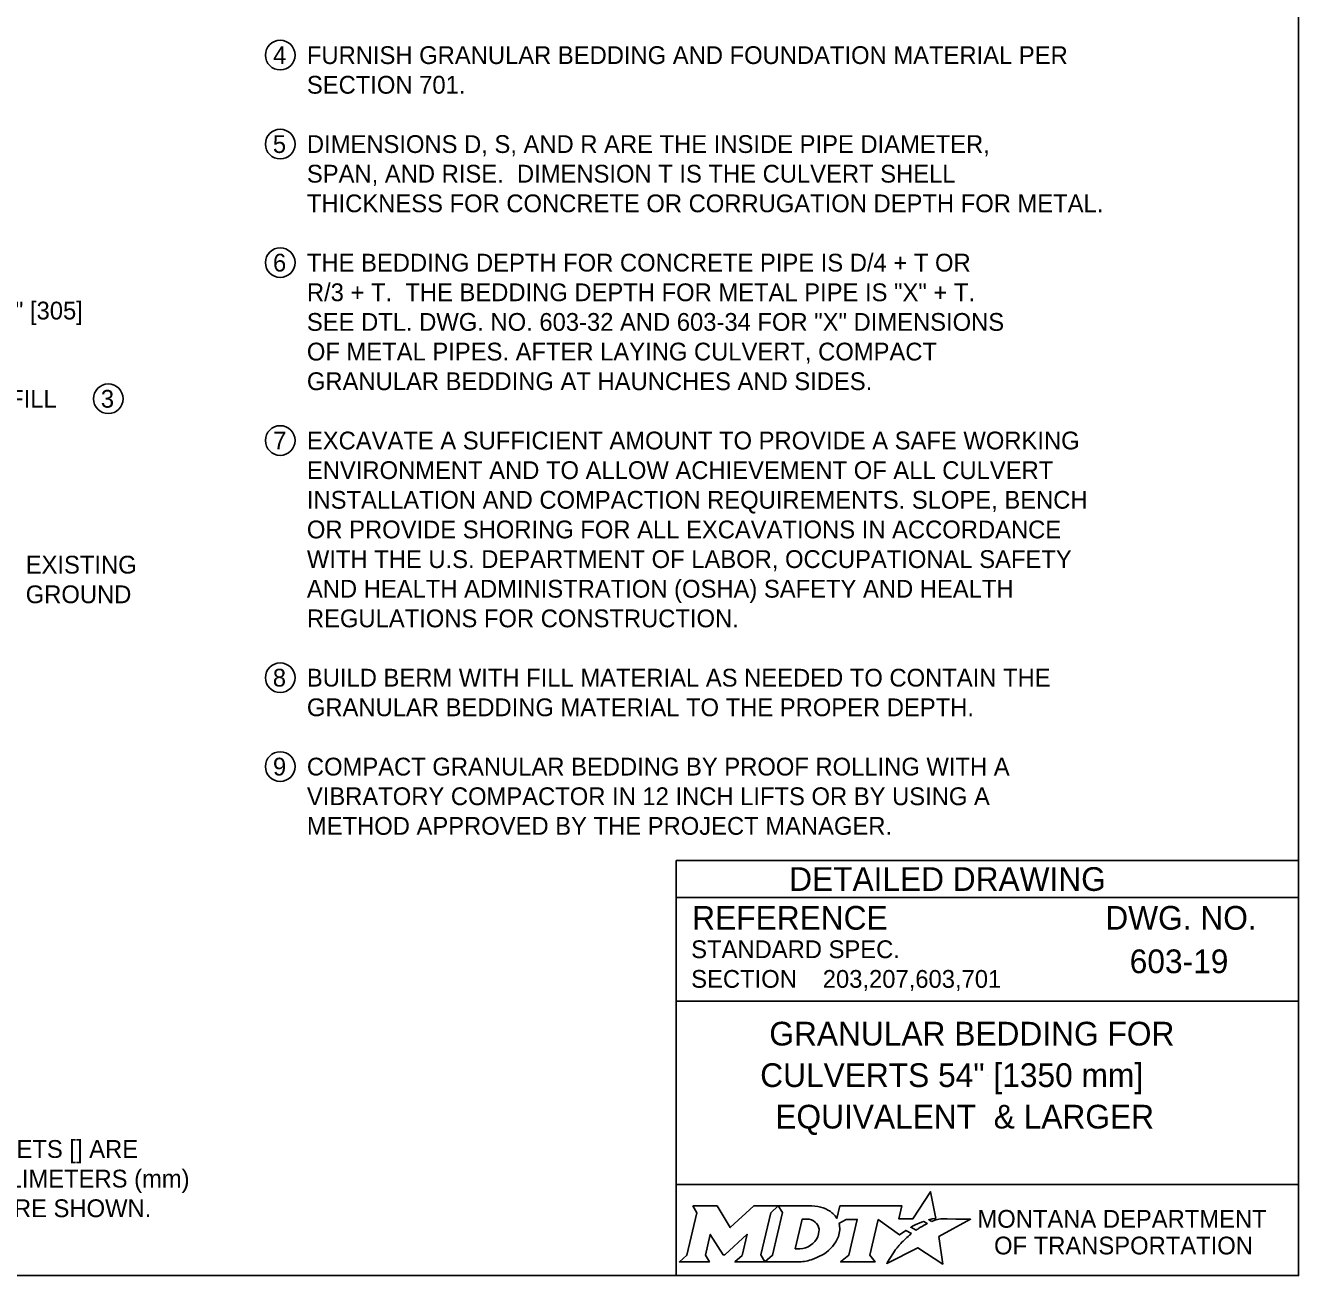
# Model space of a CAD drawing. Extents: x 49991.4 to 50021, y 49987.6 to 50011.4.
# Drawn here: x 50016.641 to 50020.938, y 49999.886 to 50004.102 of the extents above; entities that cross this region are included whole.
import ezdxf

# ---------------------------------------------------------------- set-up
doc = ezdxf.new("R2010")
doc.units = 0
for name, color, linetype in [('Default', 7, 'Continuous'), ('Level 1', 7, 'Continuous'), ('Level 2', 7, 'Continuous'), ('Level 4', 7, 'Continuous')]:
    doc.layers.add(name, color=color, linetype=linetype)

msp = doc.modelspace()

# ---------------------------------------------------------------- linework, layer by layer
at = {"layer": 'Default'}
for points in [[(50019.7003, 50000.0679), (50019.69, 50000.0735), (50019.7016, 50000.0763), (50019.7132, 50000.0783), (50019.6958, 50000.1684), (50019.6363, 50000.0771), (50019.589, 50000.0764), (50019.5993, 50000.1205), (50019.3901, 50000.1206), (50019.38, 50000.0781), (50019.3742, 50000.0864)], [(50018.8933, 50000.1206), (50018.9074, 50000.0972), (50018.8739, 49999.9539), (50018.8482, 49999.9314), (50018.9498, 49999.9314), (50018.9363, 49999.9542), (50018.9525, 50000.0243), (50018.9962, 49999.9553), (50019.0015, 49999.9553), (50019.0766, 50000.0248), (50019.0602, 49999.9537), (50019.0355, 49999.9317), (50019.1371, 49999.9317), (50019.1233, 49999.955), (50019.1565, 50000.0974)], [(50019.1565, 50000.0974), (50019.1818, 50000.1206), (50019.0994, 50000.1206), (50019.0198, 50000.0476), (50018.9753, 50000.1203), (50018.8933, 50000.1206)], [(50019.2954, 50000.1206), (50019.1818, 50000.1206), (50019.1965, 50000.0977), (50019.1626, 49999.9539), (50019.1371, 49999.9317), (50019.2477, 49999.9317)], [(50019.3194, 50000.0339), (50019.3182, 50000.0258), (50019.315, 50000.0165), (50019.3108, 50000.0083), (50019.3052, 50000.0008), (50019.2987, 49999.9939), (50019.2908, 49999.9876), (50019.2825, 49999.9829), (50019.2734, 49999.979), (50019.2643, 49999.9767), (50019.2551, 49999.9758), (50019.2392, 49999.9758), (50019.2628, 50000.0758), (50019.2788, 50000.0758), (50019.2864, 50000.0752), (50019.294, 50000.0733), (50019.3006, 50000.0703), (50019.3067, 50000.0661), (50019.3115, 50000.0611), (50019.3152, 50000.0551), (50019.3179, 50000.0489), (50019.3195, 50000.0415), (50019.3195, 50000.0385), (50019.3194, 50000.0339)], [(50019.3868, 50000.0615), (50019.4114, 50000.0746), (50019.4483, 50000.0746), (50019.4197, 49999.9541), (50019.3922, 49999.9314), (50019.5084, 49999.9314), (50019.4914, 49999.9543), (50019.5196, 50000.0745), (50019.5909, 50000.0228), (50019.612, 50000.0379), (50019.6317, 50000.027)], [(50019.5759, 49999.9711), (50019.5606, 49999.9467), (50019.5559, 49999.9392), (50019.5501, 49999.9306), (50019.5478, 49999.9263), (50019.6531, 49999.9794), (50019.737, 49999.9243), (50019.7239, 50000.017), (50019.8308, 50000.0754), (50019.7815, 50000.0762), (50019.7514, 50000.0766), (50019.7306, 50000.0769), (50019.7238, 50000.0754), (50019.7189, 50000.0742), (50019.7105, 50000.0719), (50019.7003, 50000.0679)], [(50019.6499, 50000.0403), (50019.6475, 50000.0386), (50019.6292, 50000.0482), (50019.6395, 50000.0539), (50019.6436, 50000.0561), (50019.6522, 50000.0601), (50019.6579, 50000.0627), (50019.6658, 50000.0657), (50019.6731, 50000.0684), (50019.6849, 50000.061), (50019.6809, 50000.0589), (50019.6763, 50000.0564), (50019.6721, 50000.0542), (50019.6671, 50000.0513), (50019.6652, 50000.0502), (50019.6625, 50000.0486), (50019.66, 50000.0472), (50019.6577, 50000.0456), (50019.6551, 50000.0438), (50019.6524, 50000.042), (50019.6499, 50000.0403)], [(50019.5898, 49999.9872), (50019.5898, 49999.9872)], [(50019.2934, 49999.939), (50019.3018, 49999.9416), (50019.3148, 49999.947), (50019.3352, 49999.958)]]:
    msp.add_lwpolyline(points, dxfattribs=at)
for centre, radius, start, end in [((50019.3185, 50000.0422), 0.0709, 339.5329, 15.8582), ((50019.2745, 50000.0595), 0.1183, 300.9103, 339.1383)]:
    msp.add_arc(centre, radius, start, end, dxfattribs=at)
for centre, major_axis, ratio, start_param, end_param in [((50019.2933, 50000.0732), (0.0834, -0.0037), 0.568097, 0.61298, 1.570796), ((50019.3489, 50000.0805), (0.0361, -0.0295), 0.469099, 1.225588, 1.570796), ((50019.5996, 49999.9974), (-0.0098, -0.0102), 0.016458, 3.141593, 6.279097), ((50019.6206, 50000.0173), (-0.0112, -0.0097), 0.021651, 3.157348, 6.283185), ((50019.5829, 49999.9791), (-0.00694, -0.00806), 0.008222, 0, 3.137361), ((50019.248, 50000.08), (0, 0.1484), 0.987302, 3.139398, 3.456847)]:
    msp.add_ellipse(centre, major_axis=major_axis, ratio=ratio, start_param=start_param, end_param=end_param, dxfattribs=at)
at = {"layer": 'Level 1'}
msp.add_lwpolyline([(50020.9378, 50008.1646), (50009.7374, 50008.1646), (50009.7374, 49999.8856), (50020.9378, 49999.8856)], close=True, dxfattribs=at)
at = {"layer": 'Level 2'}
for centre in [(50017.5011, 50004.0023), (50017.5011, 50003.7023), (50017.5011, 50003.3023), (50016.9209, 50002.8431), (50017.5011, 50002.7023), (50017.5011, 50001.9023), (50017.5011, 50001.6023)]:
    msp.add_circle(centre, 0.05, dxfattribs=at)
at = {"layer": 'Level 4'}
for p, q in [((50020.9378, 50001.2856), (50018.8378, 50001.2856)), ((50018.8378, 50001.2856), (50018.8378, 49999.8856)), ((50020.9378, 50001.1606), (50018.8378, 50001.1606)), ((50020.5739, 50000.9455), (50020.5739, 50000.9455)), ((50019.3321, 50000.8861), (50019.3321, 50000.8861)), ((50020.9378, 50000.8106), (50018.8378, 50000.8106)), ((50019.8878, 50000.5615), (50019.8878, 50000.5615)), ((50020.9378, 50000.1925), (50018.8378, 50000.1925))]:
    msp.add_line(p, q, dxfattribs=at)

# ---------------------------------------------------------------- texts
at = {"layer": 'Default'}
for s, p in [('MONTANA DEPARTMENT', (50019.854, 50000.0468)), ('OF TRANSPORTATION', (50019.9102, 49999.9568))]:
    msp.add_text(s, height=0.06, dxfattribs=at).set_placement(p)
at = {"layer": 'Level 2'}
for s, height, p in [('4', 0.06, (50017.4771, 50003.9723)), ('FURNISH GRANULAR BEDDING AND FOUNDATION MATERIAL PER', 0.06, (50017.5911, 50003.9723)), ('SECTION 701.', 0.06, (50017.5911, 50003.8723)), ('5', 0.06, (50017.4762, 50003.6723)), ('DIMENSIONS D, S, AND R ARE THE INSIDE PIPE DIAMETER, ', 0.06, (50017.5911, 50003.6723)), ('SPAN, AND RISE.  DIMENSION T IS THE CULVERT SHELL', 0.06, (50017.5911, 50003.5723)), ('THICKNESS FOR CONCRETE OR CORRUGATION DEPTH FOR METAL.', 0.06, (50017.5911, 50003.4723)), ('6', 0.06, (50017.4766, 50003.2723)), ('THE BEDDING DEPTH FOR CONCRETE PIPE IS D/4 + T OR', 0.06, (50017.5911, 50003.2723)), ('R/3 + T.  THE BEDDING DEPTH FOR METAL PIPE IS "X" + T.', 0.06, (50017.5911, 50003.1723)), ('1\'-0" [305]', 0.06, (50016.4744, 50003.1106)), ('SEE DTL. DWG. NO. 603-32 AND 603-34 FOR "X" DIMENSIONS ', 0.06, (50017.5911, 50003.0723)), ('OF METAL PIPES. AFTER LAYING CULVERT, COMPACT', 0.06, (50017.5911, 50002.9723)), ('GRANULAR BEDDING AT HAUNCHES AND SIDES.', 0.06, (50017.5911, 50002.8723)), ('SIDE FILL', 0.06, (50016.3768, 50002.8131)), ('3', 0.06, (50016.8957, 50002.8131)), ('7', 0.06, (50017.4773, 50002.6723)), ('EXCAVATE A SUFFICIENT AMOUNT TO PROVIDE A SAFE WORKING', 0.06, (50017.5911, 50002.6723)), ('ENVIRONMENT AND TO ALLOW ACHIEVEMENT OF ALL CULVERT ', 0.06, (50017.5911, 50002.5723)), ('INSTALLATION AND COMPACTION REQUIREMENTS. SLOPE, BENCH', 0.06, (50017.5911, 50002.4723)), ('OR PROVIDE SHORING FOR ALL EXCAVATIONS IN ACCORDANCE ', 0.06, (50017.5911, 50002.3723)), ('WITH THE U.S. DEPARTMENT OF LABOR, OCCUPATIONAL SAFETY ', 0.06, (50017.5911, 50002.2723)), ('EXISTING', 0.06, (50016.6421, 50002.2535)), ('GROUND', 0.06, (50016.6421, 50002.1535)), ('AND HEALTH ADMINISTRATION (OSHA) SAFETY AND HEALTH', 0.06, (50017.5911, 50002.1723)), ('REGULATIONS FOR CONSTRUCTION.', 0.06, (50017.5911, 50002.0723)), ('8', 0.06, (50017.4761, 50001.8723)), ('BUILD BERM WITH FILL MATERIAL AS NEEDED TO CONTAIN THE', 0.06, (50017.5911, 50001.8723)), ('GRANULAR BEDDING MATERIAL TO THE PROPER DEPTH.', 0.06, (50017.5911, 50001.7723)), ('9', 0.06, (50017.4766, 50001.5723)), ('COMPACT GRANULAR BEDDING BY PROOF ROLLING WITH A', 0.06, (50017.5911, 50001.5723)), ('VIBRATORY COMPACTOR IN 12 INCH LIFTS OR BY USING A', 0.06, (50017.5911, 50001.4723)), ('METHOD APPROVED BY THE PROJECT MANAGER.', 0.06, (50017.5911, 50001.3723)), ('603-19', 0.08, (50020.368, 50000.9055)), ('203,207,603,701', 0.06, (50019.3321, 50000.8561)), ('GRANULAR BEDDING FOR', 0.08, (50019.1517, 50000.6615)), ('CULVERTS 54" [1350 mm]', 0.08, (50019.1209, 50000.5215)), ('EQUIVALENT  & LARGER', 0.08, (50019.1719, 50000.3815)), ('UNITS SHOWN IN BRACKETS [] ARE ', 0.06, (50015.6394, 50000.2825)), ('METRIC AND ARE IN MILLIMETERS (mm) ', 0.06, (50015.6394, 50000.1825)), ('UNLESS OTHER UNITS ARE SHOWN.', 0.06, (50015.6394, 50000.0825))]:
    msp.add_text(s, height=height, dxfattribs=at).set_placement(p)
at = {"layer": 'Level 4'}
for s, height, p in [('DETAILED DRAWING', 0.0799, (50019.2188, 50001.1831)), ('REFERENCE', 0.08, (50018.8914, 50001.0522)), ('DWG. NO.', 0.08, (50020.2856, 50001.0522)), ('STANDARD SPEC.', 0.06, (50018.8881, 50000.9562)), ('SECTION', 0.06, (50018.8881, 50000.8562))]:
    msp.add_text(s, height=height, dxfattribs=at).set_placement(p)

doc.saveas('drawing.dxf')
